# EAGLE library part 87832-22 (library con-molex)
Milli-Grid Header 2.00mm (.079") Pitch
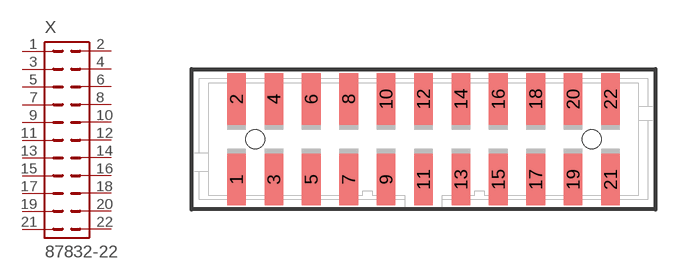
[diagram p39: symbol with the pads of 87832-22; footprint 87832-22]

Designator prefix X

## 87832-22 (OC_FARNELL: unknown; OC_NEWARK: unknown)  [87832-22]
1  1  pas
2  2  pas
3  3  pas
4  4  pas
5  5  pas
6  6  pas
7  7  pas
8  8  pas
9  9  pas
10  10  pas
11  11  pas
12  12  pas
13  13  pas
14  14  pas
15  15  pas
16  16  pas
17  17  pas
18  18  pas
19  19  pas
20  20  pas
21  21  pas
22  22  pas

## Footprint 87832-22 (pad centres in mm)
PCB Headers 2.00mm (.079") Pitch Milli-Grid Header, Vertical, Shrouded
smd 1 x 2.75: 1 -10,-2.15; 2 -10,2.15; 3 -8,-2.15; 4 -8,2.15; 5 -6,-2.15; 6 -6,2.15; 7 -4,-2.15; 8 -4,2.15; 9 -2,-2.15; 10 -2,2.15; 11 0,-2.15; 12 0,2.15; 13 2,-2.15; 14 2,2.15; 15 4,-2.15; 16 4,2.15; 17 6,-2.15; 18 6,2.15; 19 8,-2.15; 20 8,2.15; 21 10,-2.15; 22 10,2.15
hole 1 at -9,0
hole 1 at 9,0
